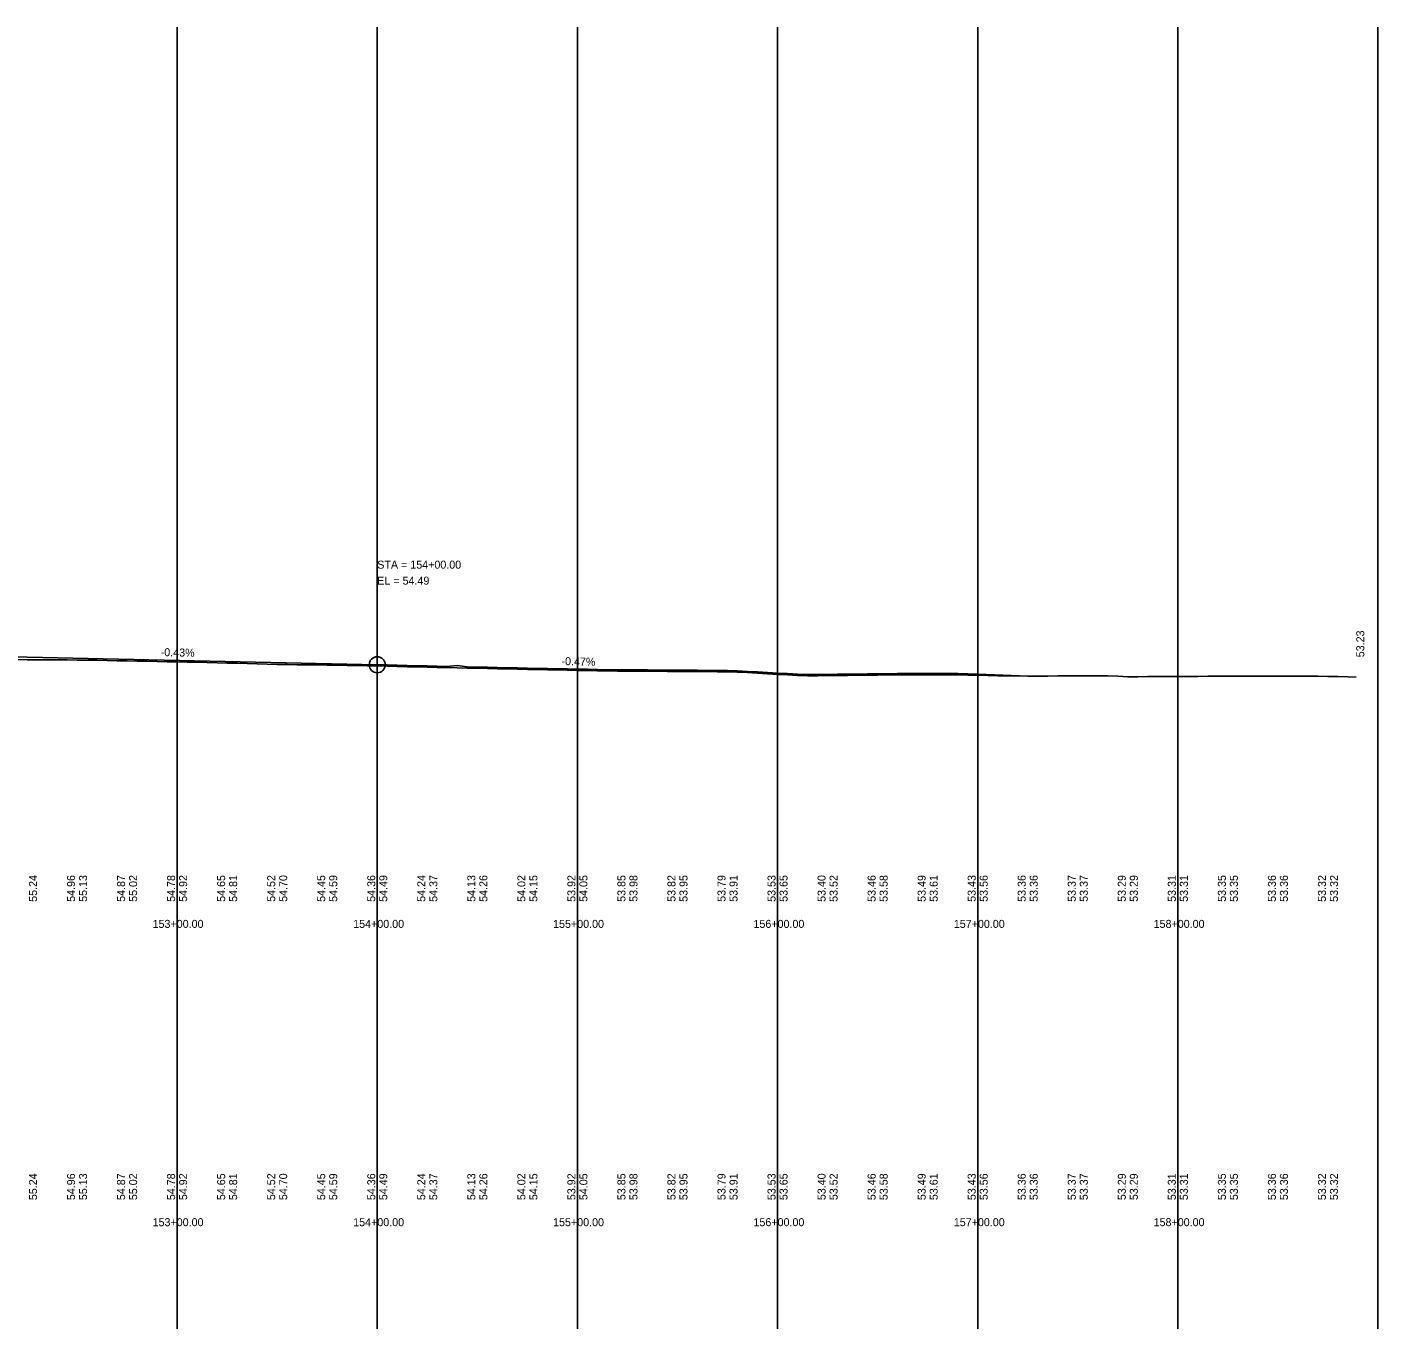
# Model space of a CAD drawing. Extents: x 3880794 to 3915434, y 287517 to 300173.
# Drawn here: x 3914376 to 3915051, y 292858 to 293504 of the extents above; entities that cross this region are included whole.
import ezdxf

# ---------------------------------------------------------------- set-up
doc = ezdxf.new("R2010")
doc.units = 0
for name, color, linetype in [('Level 1', 7, 'Continuous'), ('Level 2', 7, 'Continuous'), ('Level 30', 7, 'Continuous'), ('Level 32', 7, 'Continuous')]:
    doc.layers.add(name, color=color, linetype=linetype)

msp = doc.modelspace()

# ---------------------------------------------------------------- linework, layer by layer
at = {"layer": 'Level 1'}
for p, q in [((3914451.21, 292476.49), (3914451.21, 293504.13)), ((3914551.21, 292476.49), (3914551.21, 293504.13)), ((3914651.21, 292476.49), (3914651.21, 293504.13)), ((3914751.21, 292476.49), (3914751.21, 293504.13)), ((3914851.21, 292476.49), (3914851.21, 293504.13)), ((3914951.21, 292476.49), (3914951.21, 293504.13)), ((3915051.21, 292476.49), (3915051.21, 293504.13))]:
    msp.add_line(p, q, dxfattribs=at)
at = {"layer": 'Level 2'}
for p, q in [((3913401.21, 293210.29), (3914551.21, 293185.59)), ((3914551.21, 293185.59), (3914556.21, 293185.48)), ((3914556.21, 293185.48), (3914561.21, 293185.36)), ((3914561.21, 293185.36), (3914566.21, 293185.24)), ((3914566.21, 293185.24), (3914571.21, 293185.11)), ((3914571.21, 293185.11), (3914576.21, 293185)), ((3914576.21, 293185), (3914581.21, 293184.88)), ((3914581.21, 293184.88), (3914586.21, 293184.76)), ((3914586.21, 293184.76), (3914591.21, 293185.14)), ((3914591.21, 293185.14), (3914596.21, 293184.55)), ((3914596.21, 293184.55), (3914601.21, 293184.44)), ((3914601.21, 293184.44), (3914606.21, 293184.33)), ((3914606.21, 293184.33), (3914611.21, 293184.22)), ((3914611.21, 293184.22), (3914616.21, 293184.1)), ((3914616.21, 293184.1), (3914621.21, 293184)), ((3914621.21, 293184), (3914626.21, 293183.9)), ((3914626.21, 293183.9), (3914631.21, 293183.79)), ((3914631.21, 293183.79), (3914636.21, 293183.7)), ((3914636.21, 293183.7), (3914641.21, 293183.6)), ((3914641.21, 293183.6), (3914646.21, 293183.5)), ((3914646.21, 293183.5), (3914651.21, 293183.4)), ((3914651.21, 293183.4), (3914656.21, 293183.32)), ((3914656.21, 293183.32), (3914661.21, 293183.22)), ((3914661.21, 293183.22), (3914666.21, 293183.12)), ((3914666.21, 293183.12), (3914671.21, 293183.07)), ((3914671.21, 293183.07), (3914676.21, 293183.04)), ((3914676.21, 293183.04), (3914681.21, 293183.01)), ((3914681.21, 293183.01), (3914686.21, 293182.98)), ((3914686.21, 293182.98), (3914691.21, 293182.95)), ((3914691.21, 293182.95), (3914696.21, 293182.92)), ((3914696.21, 293182.92), (3914701.21, 293182.89)), ((3914701.21, 293182.89), (3914706.21, 293182.85)), ((3914706.21, 293182.85), (3914711.21, 293182.82)), ((3914711.21, 293182.82), (3914716.21, 293182.79)), ((3914716.21, 293182.79), (3914721.21, 293182.75)), ((3914721.21, 293182.75), (3914726.21, 293182.72)), ((3914726.21, 293182.72), (3914731.21, 293182.59)), ((3914731.21, 293182.59), (3914736.21, 293182.3)), ((3914736.21, 293182.3), (3914741.21, 293182)), ((3914741.21, 293182), (3914746.21, 293181.71)), ((3914746.21, 293181.71), (3914751.21, 293181.43)), ((3914751.21, 293181.43), (3914756.21, 293181.17)), ((3914756.21, 293181.17), (3914761.21, 293180.87)), ((3914761.21, 293180.87), (3914766.21, 293180.65)), ((3914766.21, 293180.65), (3914771.21, 293180.71)), ((3914771.21, 293180.71), (3914776.21, 293180.77)), ((3914776.21, 293180.77), (3914781.21, 293180.83)), ((3914781.21, 293180.83), (3914786.21, 293180.89)), ((3914786.21, 293180.89), (3914791.21, 293180.95)), ((3914791.21, 293180.95), (3914796.21, 293181.01)), ((3914796.21, 293181.01), (3914801.21, 293181.07)), ((3914801.21, 293181.07), (3914806.21, 293181.12)), ((3914806.21, 293181.12), (3914811.21, 293181.15)), ((3914811.21, 293181.15), (3914816.21, 293181.18)), ((3914816.21, 293181.18), (3914821.21, 293181.21)), ((3914821.21, 293181.21), (3914826.21, 293181.23)), ((3914826.21, 293181.23), (3914831.21, 293181.23)), ((3914831.21, 293181.23), (3914836.21, 293181.24)), ((3914836.21, 293181.24), (3914841.21, 293181.19)), ((3914841.21, 293181.19), (3914846.21, 293181.06)), ((3914846.21, 293181.06), (3914851.21, 293180.93)), ((3914851.21, 293180.93), (3914876.21, 293179.94)), ((3914876.21, 293179.94), (3914881.21, 293179.92)), ((3914881.21, 293179.92), (3914886.21, 293179.95)), ((3914886.21, 293179.95), (3914891.21, 293179.98)), ((3914891.21, 293179.98), (3914896.21, 293180)), ((3914896.21, 293180), (3914901.21, 293180.02)), ((3914901.21, 293180.02), (3914906.21, 293180.02)), ((3914906.21, 293180.02), (3914911.21, 293180.02)), ((3914911.21, 293180.02), (3914916.21, 293180.03)), ((3914916.21, 293180.03), (3914921.21, 293179.89)), ((3914921.21, 293179.89), (3914926.21, 293179.63)), ((3914926.21, 293179.63), (3914931.21, 293179.64)), ((3914931.21, 293179.64), (3914936.21, 293179.66)), ((3914936.21, 293179.66), (3914941.21, 293179.68)), ((3914941.21, 293179.68), (3914946.21, 293179.69)), ((3914946.21, 293179.69), (3914951.21, 293179.71)), ((3914951.21, 293179.71), (3914956.21, 293179.73)), ((3914956.21, 293179.73), (3914961.21, 293179.77)), ((3914961.21, 293179.77), (3914966.21, 293179.82)), ((3914966.21, 293179.82), (3914971.21, 293179.86)), ((3914971.21, 293179.86), (3914976.21, 293179.91)), ((3914976.21, 293179.91), (3914981.21, 293179.92)), ((3914981.21, 293179.92), (3914986.21, 293179.93)), ((3914986.21, 293179.93), (3914991.21, 293179.94)), ((3914991.21, 293179.94), (3914996.21, 293179.95)), ((3914996.21, 293179.95), (3915001.21, 293179.96)), ((3915001.21, 293179.96), (3915006.21, 293179.94)), ((3915006.21, 293179.94), (3915011.21, 293179.9)), ((3915011.21, 293179.9), (3915016.21, 293179.86)), ((3915016.21, 293179.86), (3915021.21, 293179.82)), ((3915021.21, 293179.82), (3915026.21, 293179.78)), ((3915026.21, 293179.78), (3915031.21, 293179.67)), ((3915031.21, 293179.67), (3915036.21, 293179.48)), ((3915036.21, 293179.48), (3915040.36, 293179.33))]:
    msp.add_line(p, q, dxfattribs=at)
for points in [[(3914371.21, 293188.15), (3914376.21, 293188.11), (3914381.21, 293188.08), (3914386.21, 293188.04), (3914391.21, 293188.01), (3914396.21, 293187.99), (3914401.21, 293187.95), (3914406.21, 293187.92), (3914411.21, 293187.85), (3914416.21, 293187.71), (3914421.21, 293187.61), (3914426.21, 293187.51), (3914431.21, 293187.41), (3914436.21, 293187.3), (3914441.21, 293187.2), (3914446.21, 293187.1), (3914451.21, 293187.04), (3914456.21, 293186.94), (3914461.21, 293186.8), (3914466.21, 293186.67), (3914471.21, 293186.53), (3914476.21, 293186.42), (3914481.21, 293186.3), (3914486.21, 293186.16), (3914491.21, 293186.02), (3914496.21, 293185.89), (3914501.21, 293185.78), (3914506.21, 293185.7), (3914511.21, 293185.63), (3914516.21, 293185.56), (3914521.21, 293185.48), (3914526.21, 293185.41), (3914531.21, 293185.34), (3914536.21, 293185.27), (3914541.21, 293185.2), (3914546.21, 293185.1), (3914551.21, 293184.97), (3914556.21, 293184.85), (3914561.21, 293184.73), (3914566.21, 293184.62), (3914571.21, 293184.49), (3914576.21, 293184.37), (3914581.21, 293184.25), (3914586.21, 293184.14), (3914591.21, 293184.02), (3914596.21, 293183.93), (3914601.21, 293183.82), (3914606.21, 293183.7), (3914611.21, 293183.59), (3914616.21, 293183.48), (3914621.21, 293183.37), (3914626.21, 293183.28), (3914631.21, 293183.17), (3914636.21, 293183.07), (3914641.21, 293182.97), (3914646.21, 293182.88), (3914651.21, 293182.78)], [(3914651.21, 293182.78), (3914656.21, 293182.7), (3914661.21, 293182.6), (3914666.21, 293182.5), (3914671.21, 293182.45), (3914676.21, 293182.42), (3914681.21, 293182.39), (3914686.21, 293182.36), (3914691.21, 293182.33), (3914696.21, 293182.29), (3914701.21, 293182.26), (3914706.21, 293182.22), (3914711.21, 293182.19), (3914716.21, 293182.16), (3914721.21, 293182.13), (3914726.21, 293182.1), (3914731.21, 293181.97), (3914736.21, 293181.67), (3914741.21, 293181.38), (3914746.21, 293181.08), (3914751.21, 293180.79), (3914756.21, 293180.55), (3914761.21, 293180.25), (3914766.21, 293180.02), (3914771.21, 293180.08), (3914776.21, 293180.14), (3914781.21, 293180.2), (3914786.21, 293180.26), (3914791.21, 293180.33), (3914796.21, 293180.39), (3914801.21, 293180.44), (3914806.21, 293180.49), (3914811.21, 293180.52), (3914816.21, 293180.56), (3914821.21, 293180.59), (3914826.21, 293180.6), (3914831.21, 293180.61), (3914836.21, 293180.62), (3914841.21, 293180.57), (3914846.21, 293180.44), (3914851.21, 293180.31), (3914856.21, 293180.18), (3914861.21, 293180.09), (3914866.21, 293180.04), (3914871.21, 293179.99), (3914876.21, 293179.94), (3914881.21, 293179.92), (3914886.21, 293179.95), (3914891.21, 293179.98), (3914896.21, 293180), (3914901.21, 293180.02), (3914906.21, 293180.02), (3914911.21, 293180.02), (3914916.21, 293180.03), (3914921.21, 293179.89), (3914926.21, 293179.63), (3914931.21, 293179.64), (3914936.21, 293179.66), (3914941.21, 293179.68), (3914946.21, 293179.69), (3914951.21, 293179.71), (3914956.21, 293179.73), (3914961.21, 293179.77), (3914966.21, 293179.82), (3914971.21, 293179.86), (3914976.21, 293179.91), (3914981.21, 293179.92), (3914986.21, 293179.93), (3914991.21, 293179.94), (3914996.21, 293179.95), (3915001.21, 293179.96), (3915006.21, 293179.94), (3915011.21, 293179.9), (3915016.21, 293179.86), (3915021.21, 293179.82), (3915026.21, 293179.78), (3915031.21, 293179.67), (3915036.21, 293179.48), (3915040.36, 293179.33)]]:
    msp.add_lwpolyline(points, dxfattribs=at)
msp.add_circle((3914551.21, 293185.59), 4, dxfattribs=at)

# ---------------------------------------------------------------- texts
for s, p in [('STA = 154+00.00', (3914551.21, 293233.59)), ('EL = 54.49', (3914551.21, 293225.59))]:
    msp.add_text(s, height=4, dxfattribs=at).set_placement(p)
for s, rotation, p in [('53.23', 90, (3915044.36, 293189.33)), ('-0.43%', 358.76976, (3914442.97, 293189.92)), ('-0.47%', 358.65798, (3914643.23, 293185.44))]:
    msp.add_text(s, height=4, rotation=rotation, dxfattribs=at).set_placement(p)
at = {"layer": 'Level 30'}
for s, p in [('153+00.00', (3914438.96, 293054.16)), ('153+00.00', (3914438.96, 293054.16)), ('154+00.00', (3914539.18, 293054.16)), ('154+00.00', (3914539.18, 293054.16)), ('155+00.00', (3914639.06, 293054.16)), ('155+00.00', (3914639.06, 293054.16)), ('156+00.00', (3914739.18, 293054.16)), ('156+00.00', (3914739.18, 293054.16)), ('157+00.00', (3914839.28, 293054.16)), ('157+00.00', (3914839.28, 293054.16)), ('158+00.00', (3914939.12, 293054.16)), ('158+00.00', (3914939.12, 293054.16)), ('153+00.00', (3914438.96, 292905.16)), ('153+00.00', (3914438.96, 292905.16)), ('154+00.00', (3914539.18, 292905.16)), ('154+00.00', (3914539.18, 292905.16)), ('155+00.00', (3914639.06, 292905.16)), ('155+00.00', (3914639.06, 292905.16)), ('156+00.00', (3914739.18, 292905.16)), ('156+00.00', (3914739.18, 292905.16)), ('157+00.00', (3914839.28, 292905.16)), ('157+00.00', (3914839.28, 292905.16)), ('158+00.00', (3914939.12, 292905.16)), ('158+00.00', (3914939.12, 292905.16))]:
    msp.add_text(s, height=4, dxfattribs=at).set_placement(p)
at = {"layer": 'Level 32'}
for s, p in [('55.24', (3914381.21, 293067.16)), ('54.96', (3914400.21, 293067.16)), ('55.13', (3914406.21, 293067.16)), ('54.87', (3914425.21, 293067.16)), ('55.02', (3914431.21, 293067.16)), ('54.78', (3914450.21, 293067.16)), ('54.92', (3914456.21, 293067.16)), ('54.65', (3914475.21, 293067.16)), ('54.81', (3914481.21, 293067.16)), ('54.52', (3914500.21, 293067.16)), ('54.70', (3914506.21, 293067.16)), ('54.45', (3914525.21, 293067.16)), ('54.59', (3914531.21, 293067.16)), ('54.36', (3914550.21, 293067.16)), ('54.49', (3914556.21, 293067.16)), ('54.24', (3914575.21, 293067.16)), ('54.37', (3914581.21, 293067.16)), ('54.13', (3914600.21, 293067.16)), ('54.26', (3914606.21, 293067.16)), ('54.02', (3914625.21, 293067.16)), ('54.15', (3914631.21, 293067.16)), ('53.92', (3914650.21, 293067.16)), ('54.05', (3914656.21, 293067.16)), ('53.85', (3914675.21, 293067.16)), ('53.98', (3914681.21, 293067.16)), ('53.82', (3914700.21, 293067.16)), ('53.95', (3914706.21, 293067.16)), ('53.79', (3914725.21, 293067.16)), ('53.91', (3914731.21, 293067.16)), ('53.53', (3914750.21, 293067.16)), ('53.65', (3914756.21, 293067.16)), ('53.40', (3914775.21, 293067.16)), ('53.52', (3914781.21, 293067.16)), ('53.46', (3914800.21, 293067.16)), ('53.58', (3914806.21, 293067.16)), ('53.49', (3914825.21, 293067.16)), ('53.61', (3914831.21, 293067.16)), ('53.43', (3914850.21, 293067.16)), ('53.56', (3914856.21, 293067.16)), ('53.36', (3914875.21, 293067.16)), ('53.36', (3914881.21, 293067.16)), ('53.37', (3914900.21, 293067.16)), ('53.37', (3914906.21, 293067.16)), ('53.29', (3914925.21, 293067.16)), ('53.29', (3914931.21, 293067.16)), ('53.31', (3914950.21, 293067.16)), ('53.31', (3914956.21, 293067.16)), ('53.35', (3914975.21, 293067.16)), ('53.35', (3914981.21, 293067.16)), ('53.36', (3915000.21, 293067.16)), ('53.36', (3915006.21, 293067.16)), ('53.32', (3915025.21, 293067.16)), ('53.32', (3915031.21, 293067.16)), ('55.24', (3914381.21, 292918.16)), ('54.96', (3914400.21, 292918.16)), ('55.13', (3914406.21, 292918.16)), ('54.87', (3914425.21, 292918.16)), ('55.02', (3914431.21, 292918.16)), ('54.78', (3914450.21, 292918.16)), ('54.92', (3914456.21, 292918.16)), ('54.65', (3914475.21, 292918.16)), ('54.81', (3914481.21, 292918.16)), ('54.52', (3914500.21, 292918.16)), ('54.70', (3914506.21, 292918.16)), ('54.45', (3914525.21, 292918.16)), ('54.59', (3914531.21, 292918.16)), ('54.36', (3914550.21, 292918.16)), ('54.49', (3914556.21, 292918.16)), ('54.24', (3914575.21, 292918.16)), ('54.37', (3914581.21, 292918.16)), ('54.13', (3914600.21, 292918.16)), ('54.26', (3914606.21, 292918.16)), ('54.02', (3914625.21, 292918.16)), ('54.15', (3914631.21, 292918.16)), ('53.92', (3914650.21, 292918.16)), ('54.05', (3914656.21, 292918.16)), ('53.85', (3914675.21, 292918.16)), ('53.98', (3914681.21, 292918.16)), ('53.82', (3914700.21, 292918.16)), ('53.95', (3914706.21, 292918.16)), ('53.79', (3914725.21, 292918.16)), ('53.91', (3914731.21, 292918.16)), ('53.53', (3914750.21, 292918.16)), ('53.65', (3914756.21, 292918.16)), ('53.40', (3914775.21, 292918.16)), ('53.52', (3914781.21, 292918.16)), ('53.46', (3914800.21, 292918.16)), ('53.58', (3914806.21, 292918.16)), ('53.49', (3914825.21, 292918.16)), ('53.61', (3914831.21, 292918.16)), ('53.43', (3914850.21, 292918.16)), ('53.56', (3914856.21, 292918.16)), ('53.36', (3914875.21, 292918.16)), ('53.36', (3914881.21, 292918.16)), ('53.37', (3914900.21, 292918.16)), ('53.37', (3914906.21, 292918.16)), ('53.29', (3914925.21, 292918.16)), ('53.29', (3914931.21, 292918.16)), ('53.31', (3914950.21, 292918.16)), ('53.31', (3914956.21, 292918.16)), ('53.35', (3914975.21, 292918.16)), ('53.35', (3914981.21, 292918.16)), ('53.36', (3915000.21, 292918.16)), ('53.36', (3915006.21, 292918.16)), ('53.32', (3915025.21, 292918.16)), ('53.32', (3915031.21, 292918.16))]:
    msp.add_text(s, height=4, rotation=90, dxfattribs=at).set_placement(p)

doc.saveas('drawing.dxf')
